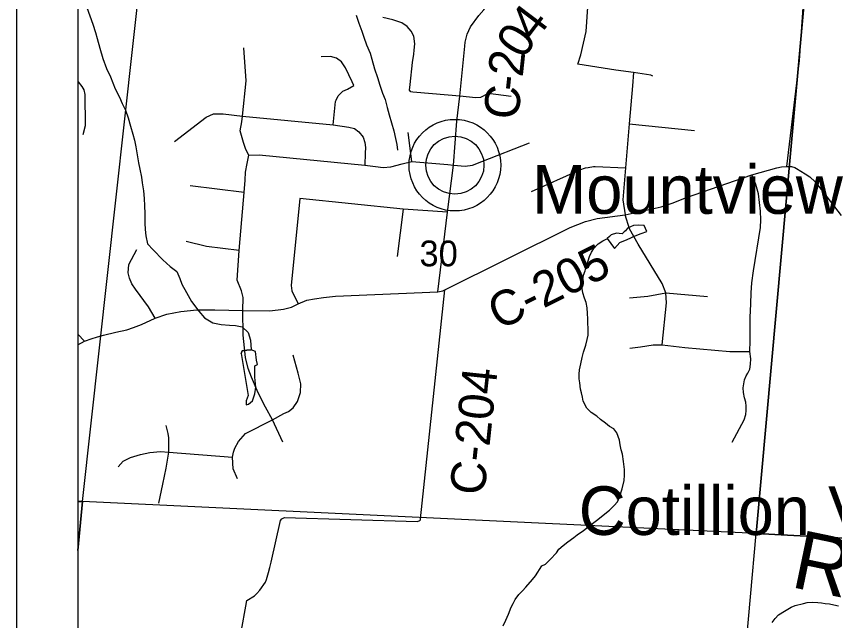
# Model space of a CAD drawing. Extents: x 0 to 34, y -2 to 22.
# Drawn here: x 2 to 3.329, y 16.823 to 17.805 of the extents above; entities that cross this region are included whole.
import ezdxf

# ---------------------------------------------------------------- set-up
doc = ezdxf.new("R2010")
doc.units = 0
for name, color, linetype in [('Default', 7, 'Continuous'), ('GM_X_County_Road', 7, 'Continuous'), ('GM_X_County_Road_Text', 7, 'Continuous'), ('GM_X_Minor_Lake', 7, 'Continuous'), ('GM_X_Minor_River', 7, 'Continuous'), ('GM_X_Minor_River_Text', 7, 'Continuous'), ('GM_X_Rail_Line', 7, 'Continuous'), ('GM_X_Section', 7, 'Continuous'), ('GM_X_Section_Text', 7, 'Continuous'), ('GM_X_Township_Road', 7, 'Continuous'), ('GM_X_Unincorporated', 7, 'Continuous'), ('GM_X_Unincorporated_Location', 7, 'Continuous'), ('GM_X_Unincorporated_Text', 7, 'Continuous'), ('SH_Cut_Line', 7, 'Continuous'), ('SH_Data', 7, 'Continuous')]:
    doc.layers.add(name, color=color, linetype=linetype)

msp = doc.modelspace()

# ---------------------------------------------------------------- linework, layer by layer
at = {"layer": 'Default'}
for points in [[(2.1, 18.1402), (2.1, 17.017), (2.1074, 17.0167), (2.2302, 18.1283)], [(2.1, 17.017), (2.1, 16.9374), (2.1074, 17.0167)]]:
    msp.add_lwpolyline(points, close=True, dxfattribs=at)
msp.add_lwpolyline([(3.1283, 16.1422), (3.2017, 16.9647), (2.1074, 17.0167), (2.1, 16.9374), (2.1, 16.4427)], dxfattribs=at)
at = {"layer": 'GM_X_County_Road'}
msp.add_line((2.1108, 17.277), (2.1, 17.2884), dxfattribs=at)
for points in [[(3.2513, 17.5609), (3.2719, 17.7328), (3.2788, 17.8269), (3.283, 17.9159), (3.2871, 17.9598), (3.2876, 17.9648)], [(2.6848, 17.3574), (2.7003, 17.4866), (2.7102, 17.5633), (2.7153, 17.6344), (2.7205, 17.6753), (2.7287, 17.7562), (2.7291, 17.7626), (2.7323, 17.7756), (2.7379, 17.7878), (2.7511, 17.8061), (2.7591, 17.8155), (2.7671, 17.8259)], [(2.6961, 17.3604), (2.8996, 17.4619), (2.9245, 17.4718), (2.9435, 17.4763), (2.9889, 17.4823), (3.0474, 17.4955), (3.0651, 17.5015), (3.0887, 17.5108), (3.1948, 17.5473), (3.2353, 17.5585), (3.243, 17.5602), (3.2513, 17.5609), (3.2589, 17.5611), (3.2643, 17.5593), (3.2672, 17.5579), (3.2814, 17.5492), (3.2887, 17.5439), (3.2974, 17.536), (3.3111, 17.5186), (3.3398, 17.4812)], [(2.4093, 16.9014), (2.4116, 16.9099), (2.4138, 16.9184), (2.4289, 16.986), (2.4313, 16.9889), (2.4355, 16.9911), (2.6512, 16.9845), (2.6529, 16.9847), (2.6544, 16.9852), (2.6554, 16.986), (2.6562, 16.9872), (2.6566, 16.9886), (2.6961, 17.3604)], [(2.6848, 17.3574), (2.6928, 17.3591), (2.6961, 17.3604)], [(2.1299, 17.2838), (2.1318, 17.2844), (2.1413, 17.2872), (2.1614, 17.2917), (2.1794, 17.2956), (2.1905, 17.2995), (2.2033, 17.3044), (2.2254, 17.3145), (2.2446, 17.3211), (2.267, 17.3252), (2.2929, 17.3279), (2.3223, 17.3279), (2.3681, 17.3268), (2.4118, 17.3266), (2.4341, 17.3293), (2.4468, 17.3324), (2.4576, 17.3379), (2.4717, 17.3437), (2.4844, 17.3458), (2.4987, 17.3481), (2.5185, 17.3501), (2.6848, 17.3574)], [(2.1, 17.2711), (2.1108, 17.277), (2.1231, 17.2816), (2.1299, 17.2838)], [(2.3728, 16.8466), (2.3745, 16.8563), (2.3866, 16.8635), (2.3904, 16.8672), (2.3957, 16.8729), (2.4045, 16.886), (2.4064, 16.8901), (2.4093, 16.9014)], [(2.3983, 16.6632), (2.3834, 16.7094), (2.3711, 16.7603), (2.3659, 16.8077), (2.3728, 16.8466)]]:
    msp.add_lwpolyline(points, dxfattribs=at)
at = {"layer": 'GM_X_Minor_Lake'}
for points in [[(2.9599, 17.4438), (2.9715, 17.4278), (2.9805, 17.4374), (2.992, 17.4421), (3.0051, 17.4482), (3.0147, 17.4521), (3.0243, 17.4556), (3.0196, 17.4649), (3.0098, 17.4659), (3.0025, 17.4649), (2.9925, 17.461), (2.9894, 17.4562), (2.9874, 17.4547), (2.9839, 17.4518), (2.9794, 17.4523), (2.9749, 17.4528), (2.9661, 17.45)], [(2.9661, 17.45), (2.9637, 17.4474), (2.9599, 17.4438)], [(2.3653, 17.2571), (2.3764, 17.1892), (2.3735, 17.1801), (2.3734, 17.1737), (2.3772, 17.1751), (2.3838, 17.1806), (2.3875, 17.1919), (2.3889, 17.2025), (2.3871, 17.2185), (2.3872, 17.2371), (2.3918, 17.2393), (2.3901, 17.2462), (2.3886, 17.2606), (2.3816, 17.2631)], [(2.3745, 17.2624), (2.367, 17.2616), (2.3653, 17.2571)], [(2.3653, 17.2571), (2.367, 17.2616), (2.3746, 17.2624)], [(2.3816, 17.2631), (2.3745, 17.2624)], [(2.3745, 17.2624), (2.3816, 17.2631)]]:
    msp.add_lwpolyline(points, dxfattribs=at)
at = {"layer": 'GM_X_Minor_River'}
for points in [[(2.1145, 17.8194), (2.1244, 17.7918), (2.1287, 17.7788), (2.1311, 17.7688), (2.1356, 17.7531), (2.1405, 17.7363), (2.1465, 17.7202), (2.153, 17.7064), (2.1605, 17.6868), (2.1674, 17.6737), (2.172, 17.6634), (2.1771, 17.6526), (2.1817, 17.6399), (2.1855, 17.6266), (2.189, 17.6136), (2.1918, 17.6036), (2.1941, 17.5929), (2.1961, 17.5796), (2.1984, 17.5666), (2.2004, 17.5567), (2.2031, 17.5437), (2.2044, 17.5342), (2.2067, 17.5212), (2.2076, 17.509), (2.208, 17.4972), (2.2085, 17.4847), (2.2088, 17.4691), (2.209, 17.4585), (2.2102, 17.4482), (2.2129, 17.4352), (2.2222, 17.4255), (2.2381, 17.4091), (2.2499, 17.3986), (2.2604, 17.3904), (2.2654, 17.3792), (2.2686, 17.3696), (2.2762, 17.3562), (2.2845, 17.3415), (2.2963, 17.326), (2.3055, 17.3152), (2.319, 17.3072), (2.3326, 17.3042), (2.3462, 17.3031), (2.3557, 17.3029), (2.3666, 17.3007), (2.3766, 17.2914), (2.3805, 17.2787), (2.3816, 17.2631)], [(2.5522, 17.8065), (2.5564, 17.7939), (2.5614, 17.7808), (2.5642, 17.7709), (2.5688, 17.7586), (2.5749, 17.7448), (2.5773, 17.7352), (2.5815, 17.7196), (2.5868, 17.7054), (2.5903, 17.6928), (2.5949, 17.6801), (2.5992, 17.6697), (2.6022, 17.6568), (2.6054, 17.6449), (2.6131, 17.6189), (2.6161, 17.6063), (2.6182, 17.5967), (2.6191, 17.5872)], [(2.7908, 16.8147), (2.7952, 16.8242), (2.7992, 16.8336), (2.804, 16.8453), (2.8072, 16.8513), (2.8103, 16.8577), (2.8162, 16.8656), (2.822, 16.8719), (2.8275, 16.8779), (2.8384, 16.8903), (2.8435, 16.8963), (2.8533, 16.9121), (2.8595, 16.915), (2.8669, 16.9225), (2.8774, 16.9333), (2.8809, 16.9393), (2.8883, 16.9456), (2.8957, 16.9516), (2.9053, 16.9586), (2.9111, 16.9627), (2.9212, 16.9698), (2.9286, 16.9757), (2.9379, 16.9828), (2.9444, 16.9876), (2.9506, 16.9924), (2.9634, 17.0025), (2.9712, 17.0103), (2.9767, 17.0163), (2.9795, 17.0238), (2.9839, 17.0375), (2.9872, 17.0511), (2.9878, 17.0594), (2.9879, 17.0686), (2.9863, 17.0819), (2.9846, 17.0937), (2.9824, 17.1006), (2.9806, 17.109), (2.9796, 17.1166), (2.9753, 17.1281), (2.9704, 17.1346), (2.9632, 17.1389), (2.9568, 17.144), (2.9489, 17.1498), (2.9429, 17.1553), (2.9339, 17.1615), (2.9264, 17.1685), (2.9208, 17.1796), (2.9194, 17.1865), (2.918, 17.1933), (2.9166, 17.1995), (2.9153, 17.2094), (2.9142, 17.2158), (2.914, 17.2238), (2.9149, 17.2307), (2.917, 17.2405), (2.9191, 17.2507), (2.9215, 17.2594), (2.9248, 17.2708), (2.9272, 17.2799), (2.9289, 17.287), (2.9287, 17.2988), (2.9285, 17.3053), (2.9282, 17.3133), (2.928, 17.3224), (2.9274, 17.3312), (2.9257, 17.3399), (2.9227, 17.3472), (2.9199, 17.356), (2.9185, 17.3663), (2.9199, 17.3773), (2.9215, 17.3845), (2.9239, 17.3917), (2.9256, 17.3981), (2.9288, 17.4075), (2.9312, 17.4147), (2.934, 17.4219), (2.9391, 17.4294), (2.945, 17.4354), (2.9527, 17.4402), (2.96, 17.4439)], [(3.2278, 16.8202), (3.2325, 16.8266), (3.2379, 16.8326), (3.2476, 16.8389), (3.2588, 16.8451), (3.265, 16.8477), (3.2788, 16.8512), (3.2845, 16.8527), (3.2937, 16.8532), (3.3021, 16.8527), (3.3078, 16.8522), (3.3139, 16.851), (3.3208, 16.8505), (3.328, 16.8492), (3.3356, 16.8472)]]:
    msp.add_lwpolyline(points, dxfattribs=at)
at = {"layer": 'GM_X_Rail_Line'}
msp.add_lwpolyline([(3.6832, 17.9108), (3.2869, 17.9604), (2.9298, 18.0171), (2.3446, 18.1102), (2.1, 18.1368), (2.1, 16.3648), (2.1342, 16.3571), (2.2291, 16.3515), (2.5217, 16.3621), (2.6166, 16.3275), (2.9069, 16.2111), (3.202, 16.0321), (3.297, 15.9555), (3.6339, 15.5717)], dxfattribs=at)
at = {"layer": 'GM_X_Section'}
for points in [[(3.2914, 17.96), (3.2017, 16.9647), (2.1074, 17.0167), (2.2302, 18.1283)], [(4.2197, 17.8557), (4.1192, 16.9159), (3.2017, 16.9647), (3.2914, 17.96)], [(4.1192, 16.9159), (4.012, 15.9002), (3.2406, 16.0402), (3.231, 16.0514), (3.2225, 16.0599), (3.2118, 16.0701), (3.2044, 16.0774), (3.197, 16.0844), (3.1881, 16.0918), (3.1769, 16.1008), (3.1658, 16.1098), (3.1569, 16.1176), (3.1469, 16.1266), (3.1398, 16.1328), (3.1309, 16.1402), (3.1283, 16.1422), (3.2017, 16.9647)]]:
    msp.add_lwpolyline(points, close=True, dxfattribs=at)
at = {"layer": 'GM_X_Township_Road'}
for p, q in [((2.9952, 17.6304), (3.1016, 17.6195)), ((2.6426, 17.5691), (2.6364, 17.6161)), ((2.3702, 17.5188), (2.2821, 17.5295)), ((2.6282, 17.4916), (2.6185, 17.415)), ((2.2474, 17.0972), (2.3511, 17.0887))]:
    msp.add_line(p, q, dxfattribs=at)
for points in [[(3.0341, 17.7077), (3.0308, 17.7095), (3.0026, 17.7134), (2.9738, 17.7173), (2.9123, 17.7269), (2.9168, 17.7425), (2.9255, 17.7799), (2.9285, 17.8195), (2.9273, 17.8309)], [(2.6455, 17.7436), (2.6464, 17.7496), (2.6472, 17.7602), (2.6457, 17.7724), (2.6413, 17.7806), (2.6347, 17.7885), (2.6259, 17.7945), (2.6117, 17.7993), (2.5951, 17.8027)], [(2.3661, 17.6337), (2.3675, 17.6429), (2.3731, 17.6999), (2.3694, 17.7539)], [(2.5147, 17.6286), (2.5186, 17.6663), (2.5194, 17.6686), (2.5228, 17.6755), (2.5302, 17.6834), (2.538, 17.6867), (2.5484, 17.6926), (2.5453, 17.6984), (2.5345, 17.7211), (2.5284, 17.7308), (2.5201, 17.7368), (2.5102, 17.7395), (2.495, 17.739)], [(2.8036, 17.6747), (2.7663, 17.6797), (2.7539, 17.6729), (2.7461, 17.6723), (2.7205, 17.6753), (2.6504, 17.6811), (2.6441, 17.6815), (2.6409, 17.6821), (2.6387, 17.6851), (2.6399, 17.6943), (2.6435, 17.7296), (2.6455, 17.7436)], [(3.0026, 17.7134), (3.0009, 17.692), (2.9952, 17.6304), (2.9895, 17.559), (2.9849, 17.5066), (2.9889, 17.4823)], [(2.1086, 17.6128), (2.1122, 17.6273), (2.112, 17.6779), (2.1099, 17.6853), (2.1068, 17.6909), (2.1009, 17.6984), (2.1, 17.6989)], [(2.2566, 17.6015), (2.3083, 17.6409), (2.3203, 17.6467), (2.336, 17.6462), (2.3675, 17.6429), (2.5147, 17.6286), (2.5403, 17.625), (2.5492, 17.6225), (2.5564, 17.6174), (2.5634, 17.6083), (2.5663, 17.5998), (2.5673, 17.592), (2.5667, 17.5827), (2.5659, 17.5629)], [(2.4329, 17.1132), (2.416, 17.1495), (2.4048, 17.1699), (2.3929, 17.1932), (2.3819, 17.2185), (2.3768, 17.2326), (2.372, 17.2509), (2.3684, 17.2872), (2.3681, 17.3268), (2.3686, 17.3482), (2.3657, 17.3588), (2.3587, 17.3762), (2.3618, 17.4245), (2.3636, 17.4433), (2.3702, 17.5188), (2.3716, 17.5388), (2.3723, 17.5518), (2.3749, 17.5659), (2.3774, 17.5794), (2.3727, 17.5885), (2.369, 17.5998), (2.3638, 17.619), (2.3661, 17.6337)], [(2.7006, 17.5642), (2.7102, 17.5633), (2.7288, 17.5613), (2.7412, 17.5633), (2.756, 17.5691), (2.8336, 17.5996)], [(2.3774, 17.5794), (2.3945, 17.5798), (2.5659, 17.5629), (2.5836, 17.5609), (2.596, 17.5592), (2.6084, 17.5605), (2.6265, 17.5654), (2.6426, 17.5691), (2.7006, 17.5642)], [(2.8367, 17.5204), (2.9142, 17.555), (2.9186, 17.5567), (2.9214, 17.5575), (2.9247, 17.5585), (2.9286, 17.5593), (2.9377, 17.5608), (2.9404, 17.5611), (2.9895, 17.559)], [(3.1626, 17.113), (3.182, 17.1496), (3.1847, 17.158), (3.1857, 17.1648), (3.1857, 17.1716), (3.1847, 17.1783), (3.1828, 17.185), (3.1809, 17.1941), (3.1807, 17.2015), (3.1818, 17.2078), (3.1829, 17.2143), (3.1856, 17.2208), (3.1881, 17.2255), (3.1915, 17.2319), (3.1925, 17.2397), (3.1928, 17.2488), (3.1914, 17.2603), (3.1921, 17.2779), (3.1917, 17.3157), (3.1931, 17.3377), (3.1937, 17.3559), (3.1948, 17.372), (3.1976, 17.3916), (3.2087, 17.4618), (3.2094, 17.4743), (3.2088, 17.4885), (3.2069, 17.5025), (3.2053, 17.5165), (3.2009, 17.5318), (3.1948, 17.5473)], [(2.4603, 17.5089), (2.4465, 17.3678), (2.4475, 17.359), (2.4576, 17.3379)], [(2.7003, 17.4866), (2.6282, 17.4916), (2.4603, 17.5089)], [(3.049, 17.2715), (3.0562, 17.3396), (3.055, 17.3556), (3.0489, 17.3711), (3.0099, 17.4349), (2.9961, 17.4596), (2.9889, 17.4823)], [(2.3618, 17.4245), (2.3087, 17.4308), (2.2756, 17.439)], [(2.2254, 17.3145), (2.2148, 17.3328), (2.1936, 17.3617), (2.1877, 17.3705), (2.1839, 17.3798), (2.1814, 17.3884), (2.1828, 17.4017), (2.1959, 17.426)], [(2.9961, 17.3474), (3.0256, 17.3505), (3.055, 17.3556), (3.1226, 17.3496)], [(2.9964, 17.2658), (3.0137, 17.268), (3.0343, 17.2713), (3.049, 17.2715), (3.0859, 17.267), (3.1591, 17.2604), (3.1914, 17.2603)], [(2.3594, 17.0537), (2.3524, 17.0698), (2.3511, 17.0887), (2.3525, 17.0967), (2.3551, 17.1037), (2.3608, 17.1141), (2.3722, 17.1271), (2.416, 17.1495), (2.4347, 17.1596), (2.4422, 17.1632), (2.4496, 17.1691), (2.4566, 17.1792), (2.4616, 17.194), (2.4622, 17.208), (2.458, 17.2254), (2.4498, 17.2546)], [(2.2474, 17.0972), (2.2479, 17.106), (2.2476, 17.1123), (2.2474, 17.1205), (2.2465, 17.1271), (2.2435, 17.1405)], [(2.1655, 17.073), (2.1737, 17.0823), (2.1854, 17.0883), (2.2017, 17.0931), (2.2168, 17.0963), (2.2341, 17.0979), (2.2474, 17.0972)], [(2.2313, 17.0142), (2.2379, 17.045), (2.2432, 17.0712), (2.2467, 17.0906), (2.2474, 17.0972)]]:
    msp.add_lwpolyline(points, dxfattribs=at)
at = {"layer": 'GM_X_Unincorporated'}
for radius in [0.0744, 0.0472]:
    msp.add_circle((2.7123, 17.5631), radius, dxfattribs=at)
at = {"layer": 'GM_X_Unincorporated_Location'}
msp.add_line((2.7123, 17.5631), (2.7123, 17.5631), dxfattribs=at)
at = {"layer": 'SH_Cut_Line'}
msp.add_lwpolyline([(8.9, 20.9), (2.1, 20.9), (2.1, 16.3648), (2.1342, 16.3571), (2.2291, 16.3515), (2.5217, 16.3621), (2.6166, 16.3275), (2.9069, 16.2111), (3.202, 16.0321), (3.297, 15.9555), (3.6339, 15.5717)], dxfattribs=at)
at = {"layer": 'SH_Data'}
for p, q in [((2, 21), (2, 14)), ((2.1, 20.9), (2.1, 14.1))]:
    msp.add_line(p, q, dxfattribs=at)

# ---------------------------------------------------------------- texts
at = {"layer": 'GM_X_County_Road_Text'}
for s, height, rotation, p in [('4', 0.0568, 52.8829, (2.8422, 17.7618)), ('0', 0.0568, 57.1936, (2.8239, 17.7333)), ('2', 0.0568, 83.8697, (2.8224, 17.705)), ('-', 0.0568, 83.9255, (2.82, 17.6818)), ('C', 0.0568, 83.9372, (2.815, 17.6354)), ('C-205', 0.05682, 26.5652, (2.7844, 17.2942)), ('C-204', 0.05682, 83.9333, (2.76, 17.0254))]:
    msp.add_text(s, height=height, rotation=rotation, dxfattribs=at).set_placement(p)
at = {"layer": 'GM_X_Minor_River_Text'}
msp.add_text('Run', height=0.0947, rotation=348.2363, dxfattribs=at).set_placement((3.2559, 16.8784))
at = {"layer": 'GM_X_Section_Text'}
msp.add_text('30', height=0.04186, rotation=0, dxfattribs=at).set_placement((2.6548, 17.3988))
at = {"layer": 'GM_X_Unincorporated_Text'}
for s, height, p in [('Mountview', 0.07898, (2.8377, 17.4841)), ('Cotillion Village', 0.078977, (2.9135, 16.9625))]:
    msp.add_text(s, height=height, rotation=0, dxfattribs=at).set_placement(p)

doc.saveas('drawing.dxf')
